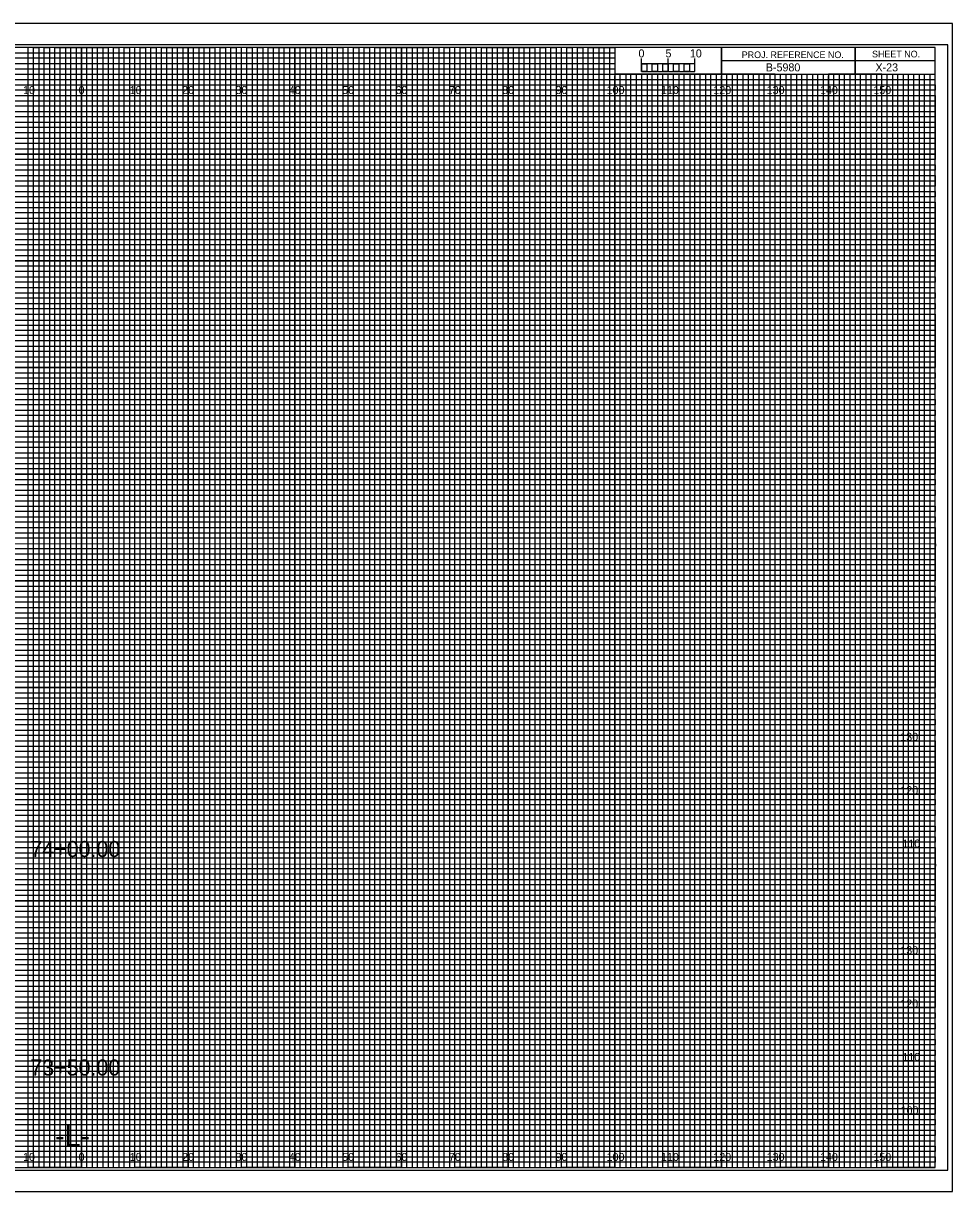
# Model space of a CAD drawing. Extents: x -13 to 323, y -5 to 1754.
# Drawn here: x 149.1 to 323.3, y 1535.5 to 1754.5 of the extents above; entities that cross this region are included whole.
import ezdxf

# ---------------------------------------------------------------- set-up
doc = ezdxf.new("R2010")
doc.units = 0
for name, color, linetype in [('Exist Cross Section Cell', 7, 'Continuous'), ('Exist XS Center Line Elevation Label', 7, 'Continuous'), ('Exist XS Ground Line', 7, 'Continuous'), ('Prop CMT Bridge Metal Rail', 7, 'Continuous'), ('Prop CMT Pvmt Course 1', 7, 'Continuous'), ('Prop CMT Pvmt Course 2', 7, 'Continuous'), ('Prop CMT Pvmt Course 3', 7, 'Continuous'), ('Prop CMT Pvmt Surface', 7, 'Continuous'), ('Prop CMT Pvmt Surface Shoulder', 7, 'Continuous'), ('Prop CMT Shld Paved Course 1', 7, 'Continuous'), ('Prop CMT Shld Paved Course 2', 7, 'Continuous'), ('Prop CMT Shld Paved Course 3', 7, 'Continuous'), ('Prop CMT Slope Grass', 7, 'Continuous'), ('Prop CMT Subgrade Earthwork', 7, 'Continuous'), ('Prop XS Shear Point Element', 7, 'Continuous'), ('Prop XS Shear Point Label', 7, 'Continuous'), ('Scratch_Level_1', 7, 'Continuous')]:
    doc.layers.add(name, color=color, linetype=linetype)

msp = doc.modelspace()

# ---------------------------------------------------------------- linework, layer by layer
at = {"layer": 'Exist XS Center Line Elevation Label'}
for points in [[(145, 1540), (155, 1540), (155, 1750), (165, 1750), (165, 1540), (175, 1540), (175, 1750), (185, 1750), (185, 1540), (195, 1540), (195, 1750), (205, 1750), (205, 1540), (215, 1540), (215, 1750), (225, 1750), (225, 1540), (235, 1540), (235, 1750), (245, 1750), (245, 1540), (255, 1540), (255, 1750), (259.93, 1750), (260, 1750), (260, 1745), (264.99, 1745), (264.99, 1540), (275, 1540), (275, 1745), (285, 1745), (285, 1540), (295, 1540), (295, 1745), (305, 1745), (305, 1540), (315, 1540), (315, 1745)], [(0, 1745), (275, 1745)], [(0, 1725), (320, 1725), (320, 1735), (0, 1735)], [(0, 1705), (320, 1705), (320, 1715), (0, 1715)], [(0, 1685), (320, 1685), (320, 1695), (0, 1695)], [(0, 1665), (320, 1665), (320, 1675), (0, 1675)], [(0, 1645), (320, 1645), (320, 1655), (0, 1655)], [(0, 1625), (320, 1625), (320, 1635), (0, 1635)], [(0, 1605), (320, 1605), (320, 1615), (0, 1615)], [(0, 1585), (320, 1585), (320, 1595), (0, 1595)], [(0, 1565), (320, 1565), (320, 1575), (0, 1575)], [(0, 1545), (320, 1545), (320, 1555), (0, 1555)]]:
    msp.add_lwpolyline(points, dxfattribs=at)
at = {"layer": 'Exist XS Ground Line'}
for p, q in [((150, 1750), (140, 1750)), ((150, 1540), (150, 1750)), ((170, 1750), (160, 1750)), ((160, 1750), (160, 1540)), ((170, 1540), (170, 1750)), ((190, 1750), (180, 1750)), ((180, 1750), (180, 1540)), ((190, 1540), (190, 1750)), ((210, 1750), (200, 1750)), ((200, 1750), (200, 1540)), ((210, 1540), (210, 1750)), ((230, 1750), (220, 1750)), ((220, 1750), (220, 1540)), ((230, 1540), (230, 1750)), ((250, 1750), (240, 1750)), ((240, 1750), (240, 1540)), ((250, 1540), (250, 1750)), ((260, 1750), (260, 1540)), ((270, 1540), (270, 1745)), ((290, 1745), (280, 1745)), ((280, 1745), (280, 1540)), ((290, 1540), (290, 1745)), ((310, 1745), (300, 1745)), ((300, 1745), (300, 1540)), ((310, 1540), (310, 1745)), ((160, 1540), (150, 1540)), ((180, 1540), (170, 1540)), ((200, 1540), (190, 1540)), ((220, 1540), (210, 1540)), ((240, 1540), (230, 1540)), ((260, 1540), (250, 1540)), ((280, 1540), (270, 1540)), ((300, 1540), (290, 1540)), ((320, 1540), (310, 1540)), ((320, 1540), (320, 1540))]:
    msp.add_line(p, q, dxfattribs=at)
for points in [[(0, 1740), (320, 1740), (320, 1730), (0, 1730)], [(0, 1720), (320, 1720), (320, 1710), (0, 1710)], [(0, 1700), (320, 1700), (320, 1690), (0, 1690)], [(0, 1680), (320, 1680), (320, 1670), (0, 1670)], [(0, 1660), (320, 1660), (320, 1650), (0, 1650)], [(0, 1640), (320, 1640), (320, 1630), (0, 1630)], [(0, 1620), (320, 1620), (320, 1610), (0, 1610)], [(0, 1600), (320, 1600), (320, 1590), (0, 1590)], [(0, 1580), (320, 1580), (320, 1570), (0, 1570)], [(0, 1560), (320, 1560), (320, 1550), (0, 1550)]]:
    msp.add_lwpolyline(points, dxfattribs=at)
at = {"layer": 'Prop CMT Pvmt Course 2'}
for p, q in [((265, 1745.49), (265, 1747.9)), ((265, 1746.9), (265, 1747.9)), ((270, 1745.49), (270, 1747.9)), ((275, 1745.49), (275, 1747.9)), ((275, 1746.9), (275, 1747.9))]:
    msp.add_line(p, q, dxfattribs=at)
for points in [[(275, 1746.9), (265, 1746.9), (265, 1745.49), (275, 1745.49)], [(265, 1746.9), (266, 1746.9), (266, 1745.49), (265, 1745.49)], [(267, 1746.9), (268, 1746.9), (268, 1745.49), (267, 1745.49)], [(269, 1746.9), (270, 1746.9), (270, 1745.49), (269, 1745.49)], [(271, 1746.9), (272, 1746.9), (272, 1745.49), (271, 1745.49)], [(273, 1746.9), (274, 1746.9), (274, 1745.49), (273, 1745.49)]]:
    msp.add_lwpolyline(points, close=True, dxfattribs=at)
at = {"layer": 'Prop CMT Pvmt Course 3'}
msp.add_lwpolyline([(-13.4, 1535.5), (323.3, 1535.5), (323.3, 1754.5), (-13.4, 1754.5)], close=True, dxfattribs=at)
at = {"layer": 'Prop CMT Pvmt Surface'}
for p, q in [((150, 1540), (150, 1750)), ((160, 1540), (160, 1750)), ((170, 1540), (170, 1750)), ((180, 1540), (180, 1750)), ((190, 1540), (190, 1750)), ((200, 1540), (200, 1750)), ((210, 1540), (210, 1750)), ((220, 1540), (220, 1750)), ((230, 1540), (230, 1750)), ((240, 1540), (240, 1750)), ((250, 1540), (250, 1750)), ((260, 1540), (260, 1744.69)), ((270, 1540), (270, 1744.69)), ((280, 1540), (280, 1744.69)), ((290, 1540), (290, 1744.69)), ((300, 1540), (300, 1744.69)), ((310, 1540), (310, 1744.69)), ((0, 1740), (320, 1740)), ((0, 1730), (320, 1730)), ((0, 1720), (320, 1720)), ((0, 1710), (320, 1710)), ((0, 1700), (320, 1700)), ((0, 1690), (320, 1690)), ((0, 1680), (320, 1680)), ((0, 1670), (320, 1670)), ((0, 1660), (320, 1660)), ((0, 1650), (320, 1650)), ((0, 1640), (320, 1640)), ((0, 1630), (320, 1630)), ((0, 1620), (320, 1620)), ((0, 1610), (320, 1610)), ((0, 1600), (320, 1600)), ((0, 1590), (320, 1590)), ((0, 1580), (320, 1580)), ((0, 1570), (320, 1570)), ((0, 1560), (320, 1560)), ((0, 1550), (320, 1550))]:
    msp.add_line(p, q, dxfattribs=at)
at = {"layer": 'Prop CMT Pvmt Surface Shoulder'}
for p, q in [((323.3, 1754.5), (-13.4, 1754.5)), ((-13.4, 1535.5), (323.3, 1535.5))]:
    msp.add_line(p, q, dxfattribs=at)
at = {"layer": 'Prop CMT Shld Paved Course 1'}
for p, q in [((0, 1749), (260, 1749)), ((260, 1747.98), (0, 1747.98)), ((260, 1749), (260, 1747.98)), ((0, 1747), (260, 1747)), ((260, 1745.89), (0, 1745.89)), ((260, 1747), (260, 1745.89)), ((0, 1744), (320, 1744))]:
    msp.add_line(p, q, dxfattribs=at)
for points in [[(0, 1743), (270, 1743), (320, 1743), (320, 1742), (0, 1742)], [(0, 1741), (320, 1741), (320, 1739), (0, 1739)], [(0, 1738), (320, 1738), (320, 1737), (0, 1736.98)], [(0, 1736), (320, 1736), (320, 1734), (0, 1734)], [(0, 1733), (320, 1733), (320, 1732), (0, 1732)], [(0, 1731), (320, 1731), (320, 1729), (0, 1729)], [(0, 1728), (320, 1728), (320, 1727), (0, 1727)], [(0, 1726), (320, 1726), (320, 1724), (0, 1724)], [(0, 1723), (320, 1723), (320, 1722), (0, 1722)], [(0, 1721), (320, 1721), (320, 1719), (0, 1719)], [(0, 1718), (320, 1718), (320, 1717), (0, 1717)], [(0, 1716), (320, 1716), (320, 1713.95), (320, 1713), (320, 1712), (0, 1712)], [(0, 1714), (320, 1714), (320, 1713), (0, 1713)], [(0, 1711), (320, 1711), (320, 1709), (0, 1709.03)], [(0, 1709.03), (320, 1709), (320, 1708), (0, 1708)], [(0, 1707), (320, 1707), (320, 1706), (0, 1706)], [(0, 1704), (320, 1704), (320, 1703), (0, 1703)], [(0, 1702), (320, 1702), (320, 1701), (0, 1701)], [(-0.07, 1698.89), (320, 1698.89), (320, 1697.88), (-0.07, 1697.88)], [(0, 1697), (320, 1697), (320, 1696), (0, 1696)], [(0, 1694), (320, 1694), (320, 1693), (0, 1693)], [(0, 1692), (320, 1692), (320, 1691), (0, 1691)], [(0, 1689), (320, 1689), (320, 1688), (0, 1688)], [(0, 1687), (320, 1687), (320, 1686), (0, 1686)], [(0, 1684), (320, 1684), (320, 1683), (0, 1683)], [(0, 1682), (320, 1682), (320, 1681), (0, 1681)], [(0, 1679), (320, 1679), (319.99, 1677.98), (0, 1678)], [(0, 1677), (320, 1677), (320, 1676), (0, 1676)], [(0, 1674), (320, 1674), (320, 1673), (0, 1673)], [(0, 1672), (320, 1672), (320, 1671), (0, 1671)], [(0, 1669), (320, 1669), (320, 1668), (0, 1668)], [(0, 1667), (320, 1667), (320, 1666), (0, 1666)], [(0, 1664), (320, 1664), (320, 1663), (0, 1663)], [(0, 1662), (320, 1662), (320, 1661), (0, 1661)], [(0, 1659), (320, 1659), (320, 1658), (0, 1658)], [(0, 1656.99), (320.07, 1656.91), (320, 1656), (0, 1656)], [(0, 1654), (320, 1654), (320, 1653), (0, 1653)], [(0, 1652), (320, 1652), (320, 1651), (0, 1651)], [(0, 1649), (320, 1649), (320, 1648), (0, 1648)], [(0, 1647), (320, 1647), (320, 1646), (0, 1646)], [(0, 1644), (320, 1644), (320, 1643), (0, 1643)], [(0, 1642), (320, 1642), (320, 1641), (0, 1641)], [(0, 1639), (320, 1639), (320, 1638), (0, 1638)], [(0, 1637), (320, 1637), (320, 1636), (0, 1636)], [(0, 1634), (320, 1634), (320, 1633), (0, 1633)], [(0, 1632), (320, 1632), (320, 1631), (0, 1631)], [(0, 1629), (320, 1629), (320, 1628), (0, 1628)], [(0, 1627), (320, 1627), (320, 1626), (0, 1626)], [(0, 1624), (320, 1624), (320, 1623), (0, 1623)], [(0, 1622), (320, 1622), (320, 1621), (0, 1621)], [(0, 1619), (320, 1619), (319.99, 1617.98), (0, 1618)], [(0, 1617), (320, 1617), (320, 1616), (0, 1616)], [(0, 1614), (320, 1614), (320, 1613), (0, 1613)], [(0, 1612), (320, 1612), (320, 1611), (0, 1611)], [(0, 1609), (320, 1609), (320, 1608), (0, 1608)], [(0, 1607), (320, 1607), (320, 1606), (0, 1606)], [(0, 1604), (320, 1604), (320, 1603), (0, 1603)], [(0, 1602), (320, 1602), (320, 1601), (0, 1601)], [(0, 1599), (320, 1599), (320, 1598), (0, 1598)], [(0, 1596.99), (320.07, 1596.91), (320, 1596), (0, 1596)], [(0, 1594), (320, 1594), (320, 1593), (0, 1593)], [(0, 1592), (320, 1592), (320, 1591), (0, 1591)], [(0, 1589), (320, 1589), (320, 1588), (0, 1588)], [(0, 1587), (320, 1587), (320, 1586), (0, 1586)], [(0, 1584), (320, 1584), (320, 1583), (0, 1583)], [(0, 1582), (320, 1582), (320, 1581), (0, 1581)], [(0, 1579), (320, 1579), (320, 1578), (0, 1578)], [(0, 1577), (320, 1577), (320, 1576), (0, 1576)], [(0, 1574), (320, 1574), (320, 1573), (0, 1573)], [(0, 1572), (320, 1572), (320, 1571), (0, 1571)], [(0, 1569), (320, 1569), (320, 1568), (0, 1568)], [(0, 1567), (320, 1567), (320, 1566), (0, 1566)], [(0, 1564), (320, 1564), (320, 1563), (0, 1563)], [(0, 1562), (320, 1562), (320, 1561), (0, 1561)], [(0, 1559), (320, 1559), (320, 1558), (0, 1558)], [(0, 1557), (320, 1557), (320, 1556), (0, 1556)], [(0, 1554), (320, 1554), (320, 1553), (0, 1553)], [(0, 1552), (320, 1552), (320, 1551), (0, 1551)], [(0, 1549), (320, 1549), (320, 1548), (0, 1548)], [(0, 1547), (320, 1547), (320, 1546), (0, 1546)], [(0, 1544), (320, 1544), (320, 1543), (0, 1543)], [(0, 1542), (320, 1542), (320, 1541), (0, 1541)]]:
    msp.add_lwpolyline(points, dxfattribs=at)
at = {"layer": 'Prop CMT Shld Paved Course 2'}
for p, q in [((305, 1750), (305, 1745)), ((305, 1745), (305, 1750)), ((280, 1747.5), (280, 1745)), ((320, 1747.49), (280, 1747.49)), ((280, 1745), (320, 1745))]:
    msp.add_line(p, q, dxfattribs=at)
for points in [[(320, 1750), (0, 1750), (0, 1540), (320, 1540)], [(280, 1750), (260, 1750), (260, 1745.03), (280, 1745.03)], [(320, 1750), (280, 1750), (280, 1745), (320, 1745)]]:
    msp.add_lwpolyline(points, close=True, dxfattribs=at)
at = {"layer": 'Prop CMT Shld Paved Course 3'}
for p, q in [((267, 1745), (266.01, 1745)), ((266.01, 1745), (266.01, 1540)), ((267, 1540), (267, 1745)), ((269, 1745), (268, 1745)), ((268, 1745), (268, 1540)), ((269, 1540), (269, 1745)), ((266.01, 1540), (265, 1540)), ((268, 1540), (267, 1540))]:
    msp.add_line(p, q, dxfattribs=at)
for points in [[(150, 1540), (151, 1540), (151, 1750), (152, 1750), (152, 1540)], [(152, 1540), (153, 1540), (153, 1750), (154, 1750), (154, 1540)], [(155, 1540), (156, 1540), (156, 1750), (157, 1750), (157, 1540)], [(157, 1540), (158, 1540), (158, 1750), (159, 1750), (159, 1540)], [(160, 1540), (161, 1540), (161, 1750), (162, 1750), (162, 1540)], [(162, 1540), (163, 1540), (163, 1750), (164, 1750), (164, 1540)], [(165, 1540), (166, 1540), (166, 1750), (167, 1750), (167, 1540)], [(167, 1540), (168, 1540), (168, 1750), (169, 1750), (169, 1540)], [(170, 1540), (171, 1540), (171, 1750), (172, 1750), (172, 1540)], [(172, 1540), (173, 1540), (173, 1750), (174, 1750), (174, 1540)], [(175, 1540), (176, 1540), (176, 1750), (177, 1750), (177, 1540)], [(177, 1540), (178, 1540), (178, 1750), (179, 1750), (179, 1540)], [(180, 1540), (181, 1540), (181, 1750), (182, 1750), (182, 1540)], [(182, 1540), (183, 1540), (183, 1750), (184, 1750), (184, 1540)], [(185, 1540), (186, 1540), (186, 1750), (187, 1750), (187, 1540)], [(187, 1540), (188, 1540), (188, 1750), (189, 1750), (189, 1540)], [(190, 1540), (191, 1540), (191, 1750), (192, 1750), (192, 1540)], [(192, 1540), (193, 1540), (193, 1750), (194, 1750), (194, 1540)], [(195, 1540), (196, 1540), (196, 1750), (197, 1750), (197, 1540)], [(197, 1540), (198, 1540), (198, 1750), (199, 1750), (199, 1540)], [(200, 1540), (201, 1540), (201, 1750), (202, 1750), (202, 1540)], [(202, 1540), (203, 1540), (203, 1750), (204, 1750), (204, 1540)], [(205, 1540), (206, 1540), (206, 1750), (207, 1750), (207, 1540)], [(207, 1540), (208, 1540), (208, 1750), (209, 1750), (209, 1540)], [(210, 1540), (211, 1540), (211, 1750), (212, 1750), (212, 1540)], [(212, 1540), (213, 1540), (213, 1750), (214, 1750), (214, 1540)], [(215, 1540), (216, 1540), (216, 1750), (217, 1750), (217, 1540)], [(217, 1540), (218, 1540), (218, 1750), (219, 1750), (219, 1540)], [(220, 1540), (221, 1540), (221, 1750), (222, 1750), (222, 1540)], [(222, 1540), (223, 1540), (223, 1750), (224, 1750), (224, 1540)], [(225, 1540), (226, 1540), (226, 1750), (227, 1750), (227, 1540)], [(227, 1540), (228, 1540), (228, 1750), (229, 1750), (229, 1540)], [(230, 1540), (231, 1540), (231, 1750), (232, 1750), (232, 1540)], [(232, 1540), (233, 1540), (233, 1750), (234, 1750), (234, 1540)], [(235, 1540), (236, 1540), (236, 1750), (237, 1750), (237, 1540)], [(237, 1540), (238, 1540), (238, 1750), (239, 1750), (239, 1540)], [(240, 1540), (241, 1540), (241, 1750), (242, 1750), (242, 1540)], [(242, 1540), (243, 1540), (243, 1750), (244, 1750), (244, 1540)], [(245, 1540), (246, 1540), (246, 1750), (247, 1750), (247, 1540)], [(247, 1540), (248, 1540), (248, 1750), (249, 1750), (249, 1540)], [(250, 1540), (251, 1540), (251, 1750), (252, 1750), (252, 1540)], [(252, 1540), (253, 1540), (253, 1750), (254, 1750), (254, 1540)], [(255, 1540), (256, 1540), (256, 1750), (257, 1750), (257, 1540)], [(257, 1540), (258, 1540), (258, 1750), (259, 1750), (259, 1540)], [(260, 1540), (261, 1540), (261, 1745), (262.02, 1745), (262.02, 1540)], [(262, 1540), (263, 1540), (263, 1745), (263.99, 1745), (263.99, 1540)], [(270, 1540), (270.98, 1540), (270.98, 1745), (272, 1745), (272, 1540)], [(272, 1540), (273, 1540), (273, 1745), (274.05, 1745), (274.05, 1540)], [(275, 1540), (276, 1540), (276, 1745), (277, 1745), (277, 1540)], [(277, 1540), (278, 1540), (278, 1745), (279, 1745), (279, 1540)], [(280, 1540), (281, 1540), (281, 1745), (282, 1745), (282, 1540)], [(282, 1540), (283, 1540), (283, 1745), (284, 1745), (284, 1540)], [(285, 1540), (286, 1540), (286, 1745), (287, 1745), (287, 1540)], [(287, 1540), (288, 1540), (288, 1745), (289, 1745), (289, 1540)], [(290, 1540), (291, 1540), (291, 1745), (292, 1745), (292, 1540)], [(292, 1540), (293, 1540), (293, 1745), (294, 1745), (294, 1540)], [(295, 1540), (296, 1540), (296, 1745), (297, 1745), (297, 1540)], [(297, 1540), (298, 1540), (298, 1745), (299, 1745), (299, 1540)], [(300, 1540), (301, 1540), (301, 1745), (302, 1745), (302, 1540)], [(302, 1540), (303, 1540), (303, 1745), (304, 1745), (304, 1540)], [(305, 1540), (306, 1540), (306, 1745), (307, 1745), (307, 1540)], [(307, 1540), (308, 1540), (308, 1745), (309, 1745), (309, 1540)], [(310, 1540), (311, 1540), (311, 1745), (312, 1745), (312, 1540)], [(312, 1540), (313, 1540), (313, 1745), (314, 1745), (314, 1540)], [(315, 1540), (316, 1540), (316, 1745), (317, 1745), (317, 1540)], [(317, 1540), (318, 1540), (318, 1745), (319, 1745), (319, 1540)]]:
    msp.add_lwpolyline(points, dxfattribs=at)
at = {"layer": 'Prop CMT Subgrade Earthwork'}
msp.add_lwpolyline([(-10.8, 1539.5), (322.4, 1539.5), (322.4, 1750.5), (-10.8, 1750.5)], close=True, dxfattribs=at)

# ---------------------------------------------------------------- texts
at = {"layer": 'Exist Cross Section Cell'}
for s, p in [('10', (149.04, 1741.25)), ('0', (159.45, 1741.25)), ('0', (159.45, 1741.25)), ('10', (169.04, 1741.25)), ('20', (178.86, 1741.25)), ('30', (188.86, 1741.25)), ('40', (198.86, 1741.25)), ('50', (208.86, 1741.25)), ('60', (218.86, 1741.25)), ('70', (228.86, 1741.25)), ('80', (238.86, 1741.25)), ('90', (248.86, 1741.25)), ('100', (258.44, 1741.25)), ('110', (268.62, 1741.25)), ('120', (278.44, 1741.25)), ('130', (288.44, 1741.25)), ('140', (298.44, 1741.25)), ('150', (308.44, 1741.25)), ('10', (149.04, 1541.25)), ('0', (159.45, 1541.25)), ('0', (159.45, 1541.25)), ('10', (169.04, 1541.25)), ('20', (178.86, 1541.25)), ('30', (188.86, 1541.25)), ('40', (198.86, 1541.25)), ('50', (208.86, 1541.25)), ('60', (218.86, 1541.25)), ('70', (228.86, 1541.25)), ('80', (238.86, 1541.25)), ('90', (248.86, 1541.25)), ('100', (258.44, 1541.25)), ('110', (268.62, 1541.25)), ('120', (278.44, 1541.25)), ('130', (288.44, 1541.25)), ('140', (298.44, 1541.25)), ('150', (308.44, 1541.25))]:
    msp.add_text(s, height=1.5, dxfattribs=at).set_placement(p)
at = {"layer": 'Prop CMT Bridge Metal Rail'}
for s, p in [('5', (269.47, 1748.12)), ('10', (274.04, 1748.12))]:
    msp.add_text(s, height=1.5, dxfattribs=at).set_placement(p)
at = {"layer": 'Prop CMT Pvmt Course 1'}
for s, p in [('130', (313.49, 1620)), ('120', (313.5, 1610)), ('110', (313.88, 1600)), ('130', (313.49, 1580)), ('120', (313.5, 1570)), ('110', (313.88, 1560)), ('100', (313.55, 1550))]:
    msp.add_text(s, height=1.5, dxfattribs=at).set_placement(p)
at = {"layer": 'Prop CMT Pvmt Course 2'}
msp.add_text('0', height=1.5, dxfattribs=at).set_placement((264.41, 1748.12))
at = {"layer": 'Prop CMT Shld Paved Course 2'}
for s, p in [('PROJ. REFERENCE NO.', (283.77, 1747.99)), ('SHEET NO.', (308.19, 1748.12))]:
    msp.add_text(s, height=1.25, dxfattribs=at).set_placement(p)
at = {"layer": 'Prop CMT Slope Grass'}
for s, p in [('74+00.00', (150.41, 1598.23)), ('73+50.00', (150.41, 1557.27))]:
    msp.add_text(s, height=3, dxfattribs=at).set_placement(p)
at = {"layer": 'Prop XS Shear Point Element'}
msp.add_text('-L-', height=4, dxfattribs=at).set_placement((155.06, 1544))
at = {"layer": 'Prop XS Shear Point Label'}
msp.add_text('B-5980', height=1.5, dxfattribs=at).set_placement((288.28, 1745.5))
at = {"layer": 'Scratch_Level_1'}
msp.add_text('X-23', height=1.5, dxfattribs=at).set_placement((308.83, 1745.5))

doc.saveas('drawing.dxf')
